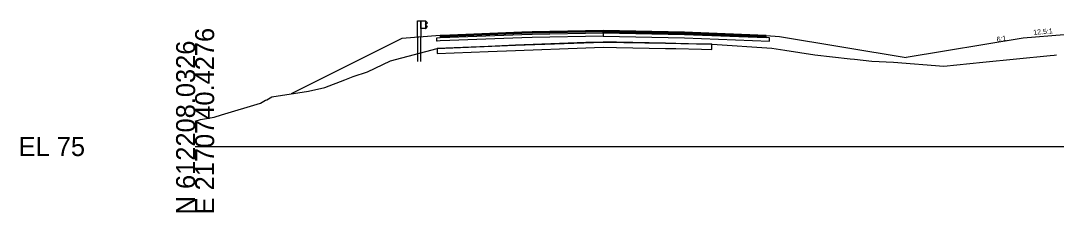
# Model space of a CAD drawing. Extents: x -26 to 1303, y -3010 to 12023.
# Drawn here: x -25.7 to 126.9, y 10990.3 to 11018.5 of the extents above; entities that cross this region are included whole.
import ezdxf

# ---------------------------------------------------------------- set-up
doc = ezdxf.new("R2010")
doc.units = 0
for name, color, linetype in [('RD_GPK_XS_Cell', 7, 'Continuous'), ('RD_PD_Final_TrvlWay', 7, 'Continuous'), ('RD_XS_Base', 7, 'Continuous'), ('RD_XS_ExGround', 7, 'Continuous'), ('RD_XS_ExPaveRet', 7, 'Continuous'), ('RD_XS_GR', 7, 'Continuous'), ('RD_XS_Greenside', 7, 'Continuous'), ('RD_XS_Pave', 7, 'Continuous'), ('RD_XS_PaveOvlay_CP', 7, 'Continuous'), ('RD_XS_TieSlope', 7, 'Continuous'), ('RD_XS_TX_ShdSlope', 7, 'Continuous'), ('RD_XS_TX_Slope', 7, 'Continuous')]:
    doc.layers.add(name, color=color, linetype=linetype)

msp = doc.modelspace()

# ---------------------------------------------------------------- linework, layer by layer
at = {"layer": 'RD_GPK_XS_Cell'}
msp.add_line((0, 11000), (150, 11000), dxfattribs=at)
at = {"layer": 'RD_PD_Final_TrvlWay'}
msp.add_lwpolyline([(33.27, 11012.54), (33.27, 11016.15), (32.77, 11016.11), (32.77, 11012.54)], dxfattribs=at)
at = {"layer": 'RD_XS_Base'}
for p, q in [((35.61, 11015.59), (35.61, 11016.04)), ((35.61, 11016.04), (35.67, 11016.04)), ((35.67, 11016.04), (36.11, 11016.06)), ((36.11, 11016.06), (37.5, 11016.11)), ((37.5, 11016.11), (48.11, 11016.53)), ((48.11, 11016.03), (37.5, 11015.61)), ((48.11, 11016.53), (49.67, 11016.57)), ((49.67, 11016.07), (48.11, 11016.03)), ((49.67, 11016.57), (60.11, 11016.77)), ((60.11, 11016.27), (49.67, 11016.07)), ((60.11, 11016.8), (60.11, 11016.93)), ((60.11, 11016.93), (60.11, 11016.37)), ((60.11, 11016.77), (60.11, 11016.93)), ((60.11, 11016.93), (60.11, 11016.27)), ((60.11, 11016.77), (60.11, 11016.8)), ((60.11, 11016.77), (60.11, 11016.35)), ((60.11, 11016.77), (60.11, 11016.27)), ((72.11, 11016.53), (60.11, 11016.77)), ((60.11, 11016.77), (60.11, 11016.77)), ((60.11, 11016.37), (60.11, 11016.27)), ((60.11, 11016.35), (60.11, 11016.27)), ((60.11, 11016.27), (60.11, 11016.27)), ((60.11, 11016.27), (60.11, 11016.27)), ((60.11, 11016.27), (72.11, 11016.03)), ((84.11, 11016.05), (72.11, 11016.53)), ((72.11, 11016.03), (84.61, 11015.53)), ((74.11, 11016.45), (74.11, 11016.45)), ((74.11, 11015.95), (74.11, 11015.95)), ((84.61, 11016.03), (84.11, 11016.05)), ((84.11, 11016.05), (84.11, 11016.05)), ((84.61, 11015.53), (84.61, 11016.03)), ((84.61, 11016.03), (84.61, 11016.03)), ((35.61, 11015.54), (35.61, 11015.59)), ((35.67, 11015.54), (35.61, 11015.54)), ((36.11, 11015.56), (35.67, 11015.54)), ((37.5, 11015.61), (36.11, 11015.56)), ((84.61, 11015.53), (84.61, 11015.53)), ((84.61, 11015.53), (84.61, 11015.53))]:
    msp.add_line(p, q, dxfattribs=at)
at = {"layer": 'RD_XS_ExGround'}
msp.add_lwpolyline([(0, 11003.73), (0.79, 11003.96), (2.79, 11004.34), (3.91, 11004.68), (9.65, 11006.39), (10.37, 11006.81), (10.56, 11006.9), (11.31, 11007.34), (16.71, 11008.17), (19.09, 11008.71), (22.04, 11009.82), (23.3, 11010.31), (25.38, 11011.03), (28.76, 11012.62), (35.68, 11014.46), (47.19, 11014.92), (60.12, 11015.4), (69.27, 11015.21), (76.14, 11015.07), (76.15, 11015.07), (84.95, 11014.48), (86.89, 11014.18), (91.31, 11013.5), (96.5, 11012.93), (97.15, 11012.85), (99.69, 11012.57), (102.89, 11012.43), (110.27, 11011.84), (116.03, 11012.41), (125.97, 11013.43), (126.55, 11013.47), (126.89, 11013.5)], dxfattribs=at)
at = {"layer": 'RD_XS_ExPaveRet'}
for points in [[(76.14, 11015.07), (76.14, 11015.07), (74.59, 11015.1), (70.83, 11015.18), (69.27, 11015.21), (62.05, 11015.36), (60.12, 11015.4), (57.56, 11015.31), (47.19, 11014.92), (43.15, 11014.76), (35.68, 11014.46), (35.68, 11013.89), (35.68, 11013.71), (43.15, 11014.01), (47.19, 11014.17), (57.56, 11014.56), (60.12, 11014.65), (62.05, 11014.61), (69.27, 11014.46), (70.83, 11014.43), (74.59, 11014.35), (76.14, 11014.32), (76.14, 11014.32), (76.14, 11014.32), (76.14, 11014.82), (76.14, 11015.07), (76.14, 11015.07)], [(76.14, 11015.07), (74.59, 11015.1), (70.83, 11015.18), (69.27, 11015.21), (62.05, 11015.36), (60.12, 11015.4), (57.56, 11015.31), (47.19, 11014.92), (43.15, 11014.76), (35.68, 11014.46), (35.68, 11013.89), (35.68, 11013.71), (43.15, 11014.01), (47.19, 11014.17), (57.56, 11014.56), (60.12, 11014.65), (62.05, 11014.61), (69.27, 11014.46), (70.83, 11014.43), (74.59, 11014.35), (76.14, 11014.32), (76.14, 11014.82), (76.14, 11015.07)]]:
    msp.add_lwpolyline(points, dxfattribs=at)
at = {"layer": 'RD_XS_GR'}
for p, q in [((32.77, 11016.11), (32.77, 11018.54)), ((32.77, 11018.54), (33.02, 11018.54)), ((33.02, 11018.54), (33.27, 11018.54)), ((33.27, 11018.54), (33.27, 11016.15)), ((33.27, 11017.37), (33.27, 11018.54)), ((33.27, 11018.54), (33.94, 11018.54)), ((33.94, 11018.54), (33.94, 11017.37)), ((34.18, 11018.28), (33.94, 11018.54)), ((33.94, 11018.54), (33.94, 11017.51)), ((33.94, 11017.96), (33.97, 11017.99)), ((34.18, 11017.7), (33.94, 11017.96)), ((33.94, 11017.51), (33.94, 11017.37)), ((33.94, 11017.37), (33.97, 11017.41)), ((33.97, 11017.99), (34.21, 11018.25)), ((33.97, 11017.41), (34.21, 11017.67)), ((34.21, 11018.25), (34.18, 11018.28)), ((34.21, 11017.67), (34.18, 11017.7)), ((33.27, 11016.15), (32.77, 11016.11)), ((33.94, 11017.37), (33.27, 11017.37))]:
    msp.add_line(p, q, dxfattribs=at)
at = {"layer": 'RD_XS_Greenside'}
for p, q in [((30.46, 11015.92), (14.15, 11007.77)), ((86.11, 11016.21), (104.76, 11013.1)), ((122, 11015.98), (104.76, 11013.1))]:
    msp.add_line(p, q, dxfattribs=at)
at = {"layer": 'RD_XS_Pave'}
for p, q in [((37.5, 11016.43), (36.11, 11016.37)), ((36.11, 11016.37), (36.11, 11016.23)), ((37.5, 11016.27), (36.11, 11016.21)), ((36.11, 11016.21), (37.5, 11016.27)), ((36.11, 11016.23), (36.11, 11016.21)), ((36.11, 11016.21), (36.11, 11016.07)), ((36.11, 11016.06), (37.5, 11016.11)), ((36.11, 11016.07), (36.11, 11016.06)), ((48.11, 11016.85), (37.5, 11016.43)), ((48.11, 11016.69), (37.5, 11016.27)), ((37.5, 11016.27), (48.11, 11016.69)), ((37.5, 11016.11), (48.11, 11016.53)), ((49.67, 11016.88), (48.11, 11016.85)), ((49.67, 11016.73), (48.11, 11016.69)), ((48.11, 11016.69), (49.67, 11016.73)), ((48.11, 11016.53), (49.67, 11016.57)), ((60.11, 11017.09), (49.67, 11016.88)), ((60.11, 11016.93), (49.67, 11016.73)), ((49.67, 11016.73), (60.11, 11016.93)), ((49.67, 11016.57), (60.11, 11016.77)), ((72.11, 11016.85), (60.11, 11017.09)), ((60.11, 11016.8), (60.11, 11016.93)), ((60.11, 11016.93), (60.11, 11016.8)), ((60.11, 11016.77), (60.11, 11016.93)), ((60.11, 11016.93), (72.11, 11016.69)), ((72.11, 11016.69), (60.11, 11016.93)), ((60.11, 11016.93), (60.11, 11016.77)), ((60.11, 11016.77), (60.11, 11016.8)), ((60.11, 11016.8), (60.11, 11016.77)), ((60.11, 11016.77), (60.11, 11016.77)), ((60.11, 11016.77), (60.11, 11016.77)), ((60.11, 11016.77), (72.11, 11016.53)), ((84.11, 11016.37), (72.11, 11016.85)), ((72.11, 11016.69), (84.11, 11016.21)), ((84.11, 11016.21), (72.11, 11016.69)), ((72.11, 11016.53), (84.11, 11016.05)), ((74.11, 11016.77), (74.11, 11016.77)), ((74.11, 11016.61), (74.11, 11016.61)), ((74.11, 11016.61), (74.11, 11016.61)), ((74.11, 11016.45), (74.11, 11016.45)), ((84.11, 11016.21), (84.11, 11016.37)), ((84.11, 11016.37), (84.11, 11016.37)), ((84.11, 11016.21), (84.11, 11016.21)), ((84.11, 11016.21), (84.11, 11016.21)), ((84.11, 11016.05), (84.11, 11016.21)), ((84.11, 11016.21), (84.11, 11016.21)), ((84.11, 11016.05), (84.11, 11016.05)), ((84.11, 11016.05), (84.11, 11016.05))]:
    msp.add_line(p, q, dxfattribs=at)
at = {"layer": 'RD_XS_PaveOvlay_CP'}
for p, q in [((36.11, 11016.37), (48.11, 11016.85)), ((48.11, 11016.85), (60.11, 11017.09)), ((60.11, 11017.09), (72.11, 11016.85)), ((72.11, 11016.85), (84.11, 11016.37))]:
    msp.add_line(p, q, dxfattribs=at)
at = {"layer": 'RD_XS_TieSlope'}
for p, q in [((36.11, 11016.37), (30.46, 11015.92)), ((84.11, 11016.37), (86.11, 11016.21)), ((128, 11016.46), (122, 11015.98))]:
    msp.add_line(p, q, dxfattribs=at)

# ---------------------------------------------------------------- texts
at = {"layer": 'RD_GPK_XS_Cell'}
for s, p in [('E 2170740.4276', (2.8, 10990)), ('N 612208.0326', (0, 10990))]:
    msp.add_text(s, height=2.8, rotation=90, dxfattribs=at).set_placement(p)
msp.add_text('EL 75', height=2.8, dxfattribs=at).set_placement((-26, 10998.6))
at = {"layer": 'RD_XS_TX_ShdSlope'}
msp.add_text('12.5:1', height=0.75, rotation=4.5739, dxfattribs=at).set_placement((123.49, 11016.45))
at = {"layer": 'RD_XS_TX_Slope'}
msp.add_text('6:1', height=0.75, rotation=9.4623, dxfattribs=at).set_placement((118.13, 11015.39))

doc.saveas('drawing.dxf')
